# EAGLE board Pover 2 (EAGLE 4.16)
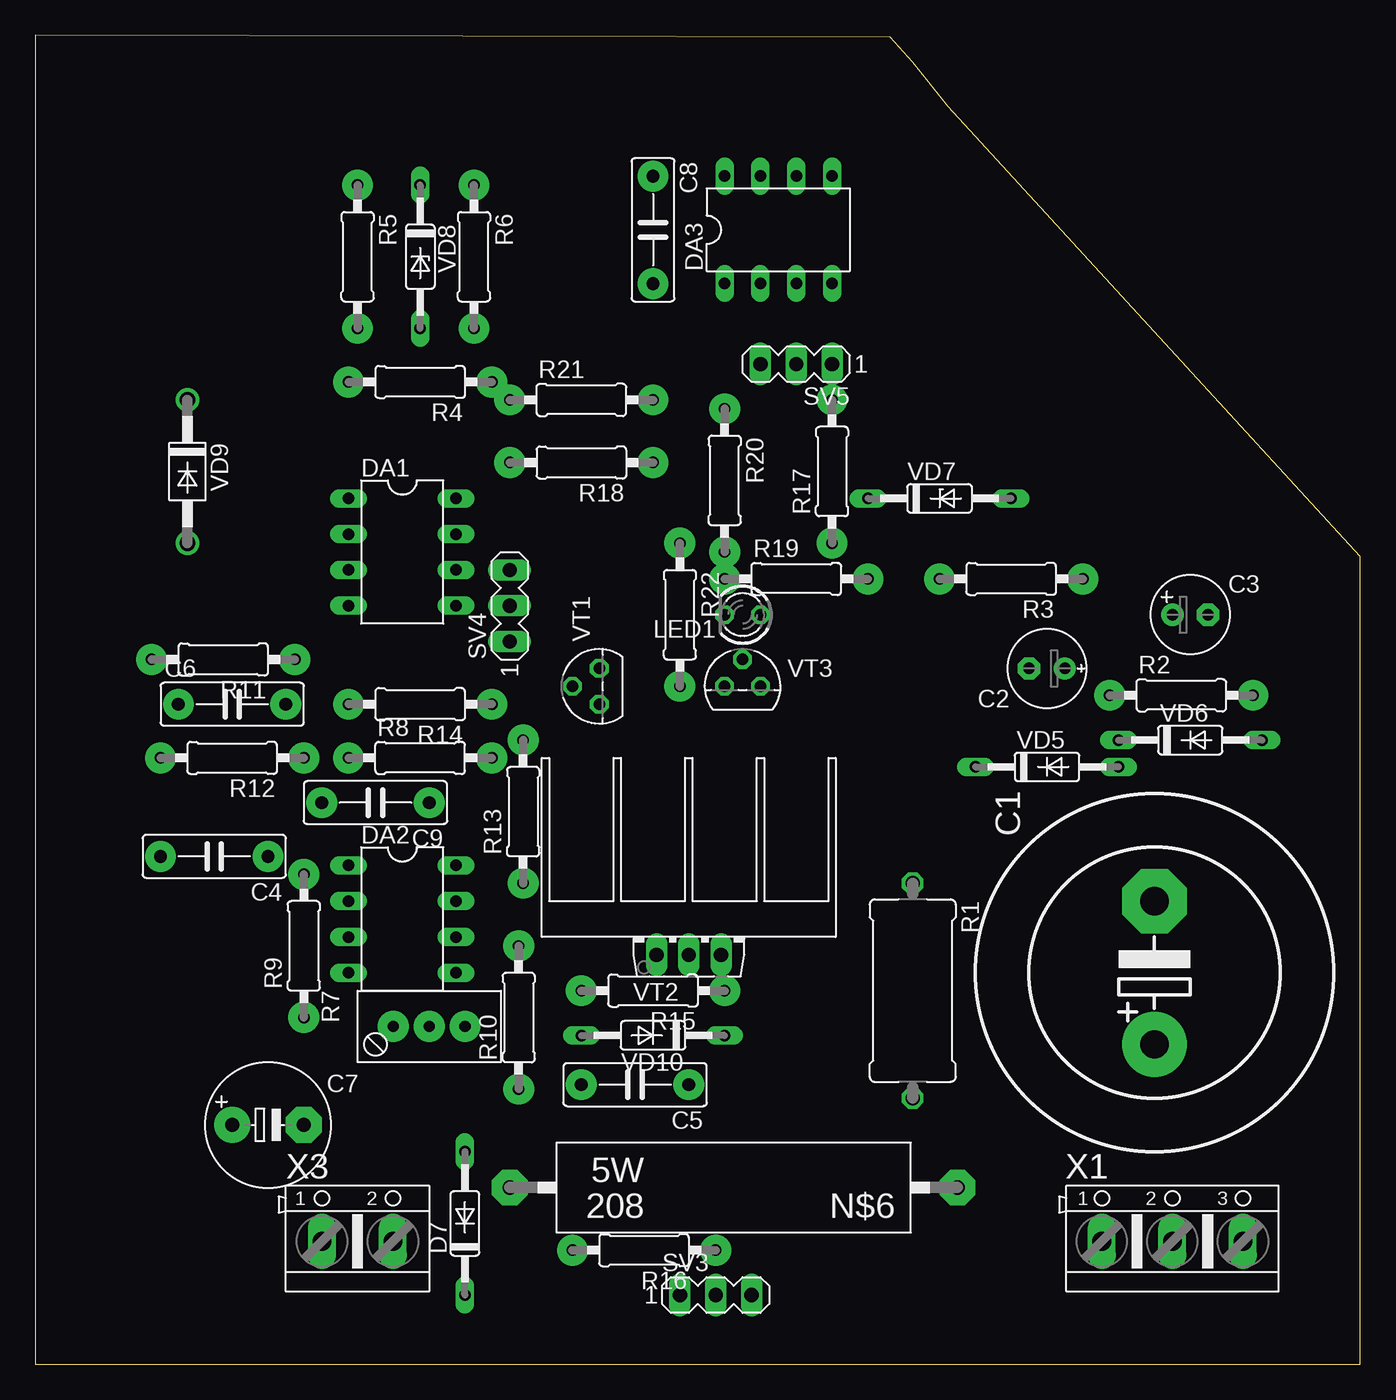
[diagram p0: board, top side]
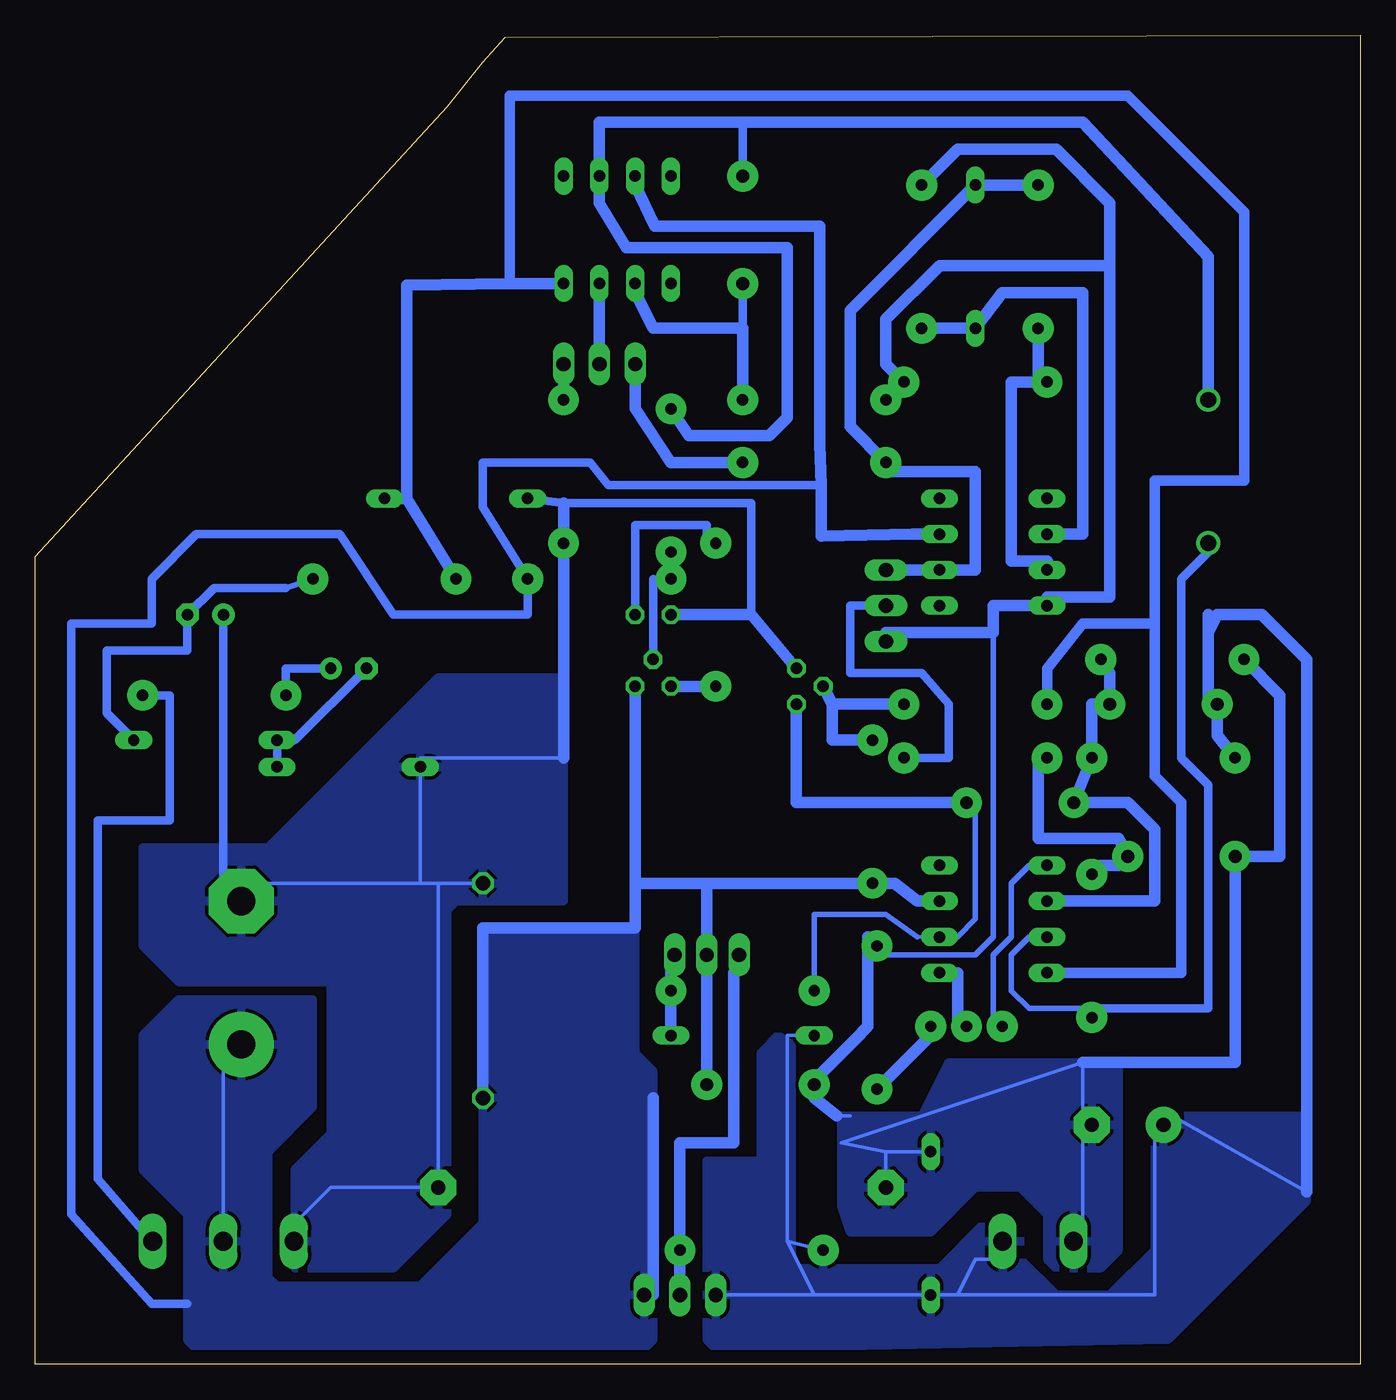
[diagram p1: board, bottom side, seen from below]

Size 93.97 x 94.28 mm. Coordinates in mm from the lower left corner, seen from the top.
Outline: 0,0 93.96,0 93.97,57.3 64.77,89.2 62.23,92.38 60.64,94.13 0,94.28 0,0
Copper layers (1*16): Top 0.035mm / dielectric 1.5mm / Bottom 0.035mm
Design rules "default": minimum track width 10mil, minimum drill 31mil, track to track 8mil, track to pad 8mil, pad to pad 8mil, via to via 8mil, smd to smd 8mil, copper to edge 40mil, drill to drill 8mil, minimum pad ring 10mil, minimum via ring 8mil, stop-mask expansion 0mil, vias tented up to drill 0mil, thermal gap 10mil
Net classes: 1 Pover: width 0.762 mm, drill 0.508 mm, clearance 0.508 mm

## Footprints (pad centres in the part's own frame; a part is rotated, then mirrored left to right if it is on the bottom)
EB25D = drill 2.007 pad 4.597 round: + -5.08,0 | drill 2.007 pad 4.597 octagon: - 5.08,0
E2,5-6E = drill 0.813 pad 1.575 round: + -1.27,0 | drill 0.813 pad 1.575 octagon: - 1.27,0
E2,5-6 = drill 0.813 pad 1.6 round: + -1.27,0 | drill 0.813 pad 1.6 octagon: - 1.27,0
C075-032X103 = drill 0.914 pad 2.184 round: 1 -3.81,0; 2 3.81,0
E5-8,5 = drill 1.016 pad 2.54 round: + -2.54,0 | drill 1.016 pad 2.54 octagon: - 2.54,0
DO35-10 = drill 0.813 long: A 5.08,0; C -5.08,0
DIL08 = drill 0.813 long: 1 -3.81,-3.81; 2 -1.27,-3.81; 3 1.27,-3.81; 4 3.81,-3.81; 5 3.81,3.81; 6 1.27,3.81; 7 -1.27,3.81; 8 -3.81,3.81
LED3MM = drill 0.813 octagon: A -1.27,0; K 1.27,0
KH208-8 = drill 1.016 pad 2.54 octagon: 1 -15.875,0; 2 15.875,0
RDH/15 = drill 1.016 octagon: 1 -7.62,0; 2 7.62,0
0207/10 = drill 0.813 pad 2.184 round: 1 -5.08,0; 2 5.08,0
RT5X10H = drill 0.8 pad 2.184 round: P$1 0,2.54; P$2 0,0; P$3 0,-2.54
MA03-1 = drill 1.016 long: 1 -2.54,0; 2 0,0; 3 2.54,0
DO35Z10 = drill 0.813 long: A 5.08,0; C -5.08,0
DO41-10 = drill 1.118 round: A 5.08,0; C -5.08,0
TO92 = drill 0.813 octagon: 1 1.27,0; 2 0,1.905; 3 -1.27,0
TO126AV = drill 1.016 long: B 2.286,-1.27; C 0,-1.27; E -2.286,-1.27
AK500/3 = drill 1.321 long: 1 -5.004,0; 2 0,0; 3 5.004,0
AK500/2 = drill 1.321 long: 1 -2.515,0; 2 2.515,0

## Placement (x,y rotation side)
C1  [EB25D]  79.37,27.77 90 top
C2  [E2,5-6E]  71.75,49.36 180 top
C3  [E2,5-6]  81.91,53.17 0 top
C4  [C075-032X103]  12.7,36.03 180 top
C5  [C075-032X103]  42.54,19.84 180 top
C6  [C075-032X103]  13.96,46.83 0 top
C7  [E5-8,5]  16.51,16.98 0 top
C8  [C075-032X103]  43.81,80.48 270 top
C9  [C075-032X103]  24.12,39.84 180 top
D7  1N4148  [DO35-10]  30.48,9.99 90 top
DA1  TL081P  [DIL08]  26.03,57.62 270 top
DA2  TL081P  [DIL08]  26.03,31.58 270 top
DA3  TL081P  [DIL08]  52.7,80.48 0 top
LED1  [LED3MM]  50.16,53.17 180 top
N$6  [KH208-8]  49.52,12.53 180 top
R1  [RDH/15]  62.23,26.5 270 top
R2  [0207/10]  81.28,47.46 0 top
R3  [0207/10]  69.21,55.72 180 top
R4  [0207/10]  27.3,69.69 180 top
R5  [0207/10]  22.86,78.57 270 top
R6  [0207/10]  31.11,78.57 270 top
R7  [RT5X10H]  27.94,23.96 90 top
R8  [0207/10]  27.3,43.02 0 top
R9  [0207/10]  19.05,29.68 90 top
R10  [0207/10]  34.29,24.6 90 top
R11  [0207/10]  13.33,50 180 top
R12  [0207/10]  13.96,43.02 180 top
R13  [0207/10]  34.6,39.2 90 top
R14  [0207/10]  27.3,46.83 180 top
R15  [0207/10]  43.81,26.5 180 top
R16  [0207/10]  43.17,8.09 180 top
R17  [0207/10]  56.51,63.34 90 top
R18  [0207/10]  38.73,63.97 180 top
R19  [0207/10]  53.97,55.72 0 top
R20  [0207/10]  48.89,62.7 270 top
R21  [0207/10]  38.73,68.41 0 top
R22  [0207/10]  45.72,53.17 270 top
RAD1  [KK13X22]  46.35,30.31 0 top
SV3  [MA03-1]  48.26,4.91 0 top
SV4  [MA03-1]  33.65,53.81 90 top
SV5  [MA03-1]  53.97,70.95 180 top
VD5  1N4148  [DO35-10]  71.75,42.38 0 top
VD6  1N4148  [DO35-10]  81.91,44.28 0 top
VD7  [DO35Z10]  64.13,61.43 0 top
VD8  [DO35Z10]  27.3,78.57 270 top
VD9  1N4004  [DO41-10]  10.79,63.34 270 top
VD10  1N4148  [DO35-10]  43.81,23.33 180 top
VT1  BC547  [TO92]  40,48.09 90 top
VT2  BD139  [TO126AV]  46.35,30.31 0 top
VT3  BC557  [TO92]  50.16,48.09 0 top
X1  [AK500/3]  80.64,8.72 0 top
X3  [AK500/2]  22.86,8.72 0 top

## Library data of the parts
C1-C9 R1-R22 = rcl
D7 VD5-VD10 = diode
DA1-DA3 = linear
LED1 = led
N$6 = resistor-power
RAD1 = heatsink
SV3-SV5 = con-lstb
VT1 = transistor
VT2 = transistor-power
VT3 = transistor-pnp
X1 X3 = con-ptr500

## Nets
N$1: R19.1 R20.2 VT3.2
N$2: R22.2 VT3.3
N$3: DA3.3 SV5.2
N$4: C8.1 DA3.6 R20.1 VD9.C
N$5: LED1.A R22.1
N$6: C1.+ C5.1 DA1.7 DA2.7 DA3.7 R1.2 R13.1 R19.2 SV3.3 VT2.C VT3.1 X1.2
N$7: C2.+ R2.1
N$8: C3.- R3.1 VD6.A
N$9: C1.- C3.+ LED1.K N$6.1 R1.1 R17.1 VD5.C VD7.C VT1.1 X1.1
N$11: C8.2 DA3.2 R21.2
N$12: R2.2 X1.3
N$14: R18.1 SV5.3
N$15: R17.2 SV5.1
N$16: DA1.6 R5.1 R18.2 SV4.3 VD8.C
N$17: DA1.3 R4.2 R5.2
N$18: DA1.2 R6.2 VD8.A
N$19: C4.1 R8.1 R9.2
N$20: R8.2 SV4.2
N$21: C4.2 C5.2 C7.- D7.A DA1.4 N$6.2 R4.1 R6.1 R10.2 R11.2 R21.1 SV4.1 X3.1
N$22: DA2.3 R9.1 VD9.A
N$24: C6.2 C9.2 DA2.2 R11.1 R12.1
N$25: R13.2 R14.1 VT1.2
N$26: R16.1 SV3.2 VT2.E
N$27: C9.1 DA2.6 R15.2 VT1.3
N$28: DA2.1 R7.P$1
N$29: DA2.5 R7.P$2
N$30: R7.P$3 R10.1
N$31: C6.1 C7.+ D7.C R12.2 R16.2 SV3.1 VD10.A X3.2
N$32: R15.1 VD10.C VT2.B
N$35 [Pover]: DA2.4 DA3.4 R3.2 R14.2 VD7.A
VD5: C2.- VD5.A VD6.C

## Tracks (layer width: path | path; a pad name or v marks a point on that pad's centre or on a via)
N$1
  Bottom 0.406: 50.16,55.72 R19.1
  Bottom 0.61: VT3.2 50.16,55.72 | R19.1 R20.2
N$2
  Bottom 0.813: R22.2 VT3.3
N$3
  Bottom 0.813: SV5.2 DA3.3
N$4
  Bottom 0.61: 43.81,88.1 C8.1
  Bottom 0.813: VD9.C 10.79,78.57 19.68,88.1 43.81,88.1 53.97,88.1 DA3.6 53.97,82.38 52.06,79.21 40.63,79.21 40.63,67.14 41.91,65.88 47.62,65.88 R20.1
N$5
  Bottom 0.61: LED1.A 51.43,59.52 46.35,59.52 46.35,58.25 R22.1
N$6
  Bottom 0.254: 50.16,4.91 SV3.3 | X1.2 80.64,21.42 C1.+
  Bottom 0.406: 51.43,83.66 DA3.7
  Bottom 0.61: 38.22,62.37 53.34,62.37 54.61,63.97 62.23,63.97 62.23,60.8 R19.2 59.05,53.17 68.58,53.17 72.38,58.89 82.55,58.89 85.72,55.72 85.72,52.54 91.44,52.54 91.44,10.63 85.72,4.28 83.18,4.28
  Bottom 0.813: DA2.7 31.43,32.85 33.02,34.12 R13.1 46.35,34.12 | 46.35,34.12 VT2.C C5.1 | R1.2 62.23,30.95 51.43,30.95 51.43,34.12 | 46.35,34.12 51.43,34.12 | 51.43,34.12 VT3.1 | DA1.7 31.75,58.89 38.22,58.76 38.22,62.37 38.35,65.24 38.35,80.73 50.03,80.73 51.43,83.66 | 50.16,18.88 50.16,4.91
  pour Bottom: 77.47,14.44 77.47,15.07 74.29,18.25 74.29,25.87 83.81,25.87 86.36,23.33 86.36,13.8 83.18,10.63 83.18,1.74 81.91,0.47 51.43,0.47 50.16,1.74 50.16,20.79 50.8,21.42 51.43,22.06 51.43,30.95 62.23,30.95 62.23,9.99 66.67,5.55 76.83,5.55 77.47,6.18 77.47,15.07
N$7
  Bottom 0.61: C2.+ 76.19,49.36 R2.1
N$8
  Bottom 0.406: 76.19,55.08 R3.1
  Bottom 0.61: VD6.A 88.9,46.19 88.9,50.63 83.18,50.63 C3.- 81.28,55.08 76.19,55.08
N$9
  Bottom 0.254: 80.64,34.12 C1.- 78.1,34.12 66.67,34.12 | 65.4,34.12 66.67,34.12 | 66.67,34.12 VD5.C 66.67,43.02 56.51,43.02 | 65.4,34.12 R1.1 | 65.4,34.12 N$6.1 73.02,12.53 75.56,9.99 X1.1
  Bottom 0.61: 80.64,34.12 C3.+ | 43.2,53.17 43.2,61.1 56.51,61.1 VD7.C
  Bottom 0.813: VT1.1 43.2,53.17 LED1.K | 56.51,61.1 R17.1 56.51,43.02
  pour Bottom: 73.02,27.14 73.02,16.34 75.56,13.8 75.56,6.82 68.58,6.82 64.77,10.63 64.77,32.22 64.13,32.85 56.51,32.85 56.51,48.73 65.4,48.73 77.47,36.66 86.36,36.66 86.36,29.68 83.81,27.14
N$11
  Bottom 0.406: 51.43,76.03 DA3.2
  Bottom 0.61: 43.81,73.5 C8.2
  Bottom 0.813: R21.2 43.81,73.5 50.16,73.5 51.43,76.03
N$12
  Bottom 0.254: X1.3 85.72,8.72
  Bottom 0.61: 85.72,8.72 89.53,13.17 89.53,38.57 84.45,38.57 84.45,47.46 R2.2
N$14
  Bottom 0.813: R18.1 48.89,63.97 51.43,67.78 SV5.3
N$15
  Bottom 0.813: R17.2 SV5.1
N$16
  Bottom 0.254: 33.65,63.34 R18.2
  Bottom 0.813: R5.1 VD8.C 36.19,74.77 36.19,66.51 R18.2 | 30.48,56.35 SV4.3 34.29,56.35 | 30.48,56.35 27.3,56.35 27.3,63.34 33.65,63.34 | 30.48,56.35 DA1.6
N$17
  Bottom 0.406: DA1.3 22.22,56.98
  Bottom 0.813: 22.22,56.98 24.76,56.98 24.76,69.69 22.86,69.69 | 22.86,69.69 R4.2 | 22.86,69.69 R5.2
N$18
  Bottom 0.813: DA1.2 19.68,58.89 19.68,76.03 25.4,76.03 VD8.A R6.2
N$19
  Bottom 0.254: C4.1 17.14,35.39 | 18.41,35.39 R9.2 | R8.1 22.86,43.02
  Bottom 0.813: 17.14,35.39 18.41,35.39 | 22.86,43.02 22.86,37.3 17.14,37.3 C4.1
N$20
  Bottom 0.254: SV4.2 33.65,54.45
  Bottom 0.61: SV4.2 36.19,53.81 36.19,49.05 31.11,49.05 29.2,46.83 29.2,43.02 R8.2
N$21
  Bottom 0.254: 34.92,30.31 R10.2 | 33.65,15.07 36.83,15.71 19.68,21.42 19.68,17.61 C7.- 19.68,16.34 19.68,9.99 X3.1 | 33.65,15.07 N$6.2 | 33.65,15.07 D7.A | 37.14,17.61 36.19,17.61 | 38.73,20.15 C5.2
  Bottom 0.406: DA1.4 22.22,54.45 | 26.03,51.91 26.03,30.31 27.3,29.04 34.92,29.04 | 33.65,51.91 SV4.1
  Bottom 0.813: R21.1 32.38,69.05 R4.1 33.65,70.95 33.65,74.13 29.84,77.94 17.78,77.94 | R6.1 28.57,86.19 21.59,86.19 17.78,82.38 17.78,77.94 | 17.78,77.94 17.78,54.45 22.22,54.45 | DA1.4 26.03,53.81 26.03,51.91 33.65,51.91 | 34.92,30.31 34.92,29.04 34.92,23.96 35.87,23.01 | 35.87,23.01 36.83,22.06 | R11.2 5.71,47.46 5.71,36.03 C4.2 8.89,21.42 19.68,21.42 | 37.14,17.61 38.73,18.88 C5.2 | 35.87,23.01 38.73,20.15
  pour Bottom: 36.83,17.61 31.11,17.61 29.2,21.42 17.14,21.42 17.14,8.09 18.41,6.82 21.59,6.82 22.22,7.45 22.22,10.63 24.12,12.53 27.3,12.53 30.48,9.36 36.19,9.36 36.83,11.26
N$22
  Bottom 0.254: 23.49,30.31 DA2.3 | 19.05,25.23 R9.1
  Bottom 0.406: 23.49,30.31 24.76,29.04 24.76,26.5 23.49,25.23 19.05,25.23
  Bottom 0.61: 19.05,25.23 10.79,25.23 10.79,41.11 12.7,43.02 12.7,55.72 10.79,57.62 VD9.A
N$24
  Bottom 0.813: R11.1 17.78,49.05 C6.2 19.05,46.83 R12.1 C9.2 16.51,39.84 14.6,37.94 14.6,32.85 DA2.2
N$25
  Bottom 0.813: R14.1 37.46,46.83 | 37.46,46.83 VT1.2 | 37.46,46.83 37.46,44.28 R13.2
N$26
  Bottom 0.254: 44.45,27.77 VT2.E | SV3.2 48.89,4.91
  Bottom 0.406: R16.1 48.26,7.45
  Bottom 0.813: 48.26,7.45 SV3.2 | R16.1 48.26,15.71 44.45,15.71 44.45,27.77
N$27
  Bottom 0.254: 31.43,30.31 DA2.6 28.57,30.31
  Bottom 0.406: R15.2 38.73,31.9 33.65,31.9 31.43,30.31 | 28.57,30.31 27.3,31.58 27.3,39.84 29.84,39.84
  Bottom 0.813: VT1.3 40,39.84 29.84,39.84 C9.1
N$28
  Bottom 0.254: 23.49,35.39 DA2.1 | 26.03,23.96 R7.P$1
  Bottom 0.406: 23.49,35.39 24.76,34.12 24.76,30.31 26.03,29.04 26.03,23.96
N$29
  Bottom 0.406: 28.57,23.96 R7.P$2
  Bottom 0.813: 28.57,23.96 28.57,27.77 DA2.5
N$30
  Bottom 0.406: 33.65,20.15 R10.1 | R7.P$3 29.84,23.96
  Bottom 0.813: 29.84,23.96 33.65,20.15
N$31
  Bottom 0.254: 40.63,8.72 40.63,23.33 VD10.A | 38.73,4.91 40.63,8.72 | 38.73,4.91 SV3.1 | 28.57,4.91 27.3,7.45 26.03,7.45 X3.2 | 28.57,4.91 D7.C 38.73,4.91 | 28.57,4.91 14.6,4.91 14.6,16.34 C7.+ 13.33,17.61 3.8,12.22 | 40.63,8.72 R16.2
  Bottom 0.61: 10.79,46.83 C6.1
  Bottom 0.813: C6.1 10.16,44.6 R12.2 | 10.79,51.91 10.79,46.83 | 10.79,51.91 10.16,53.17 6.98,53.17 3.8,50 3.8,12.22 | 10.79,53.17 10.79,51.91
  pour Bottom: 40.32,22.7 41.27,23.33 42.54,22.06 42.54,14.44 46.35,14.44 46.35,1.74 45.72,1.1 13.65,1.74 3.8,11.58 3.8,17.61 12.7,17.61 14.6,15.71 14.6,8.09 17.78,4.91 21.59,4.91 24.12,7.45 24.12,9.99 26.66,9.99 29.84,6.82 40.32,6.82
N$32
  Bottom 0.813: VD10.C R15.1 48.89,27.77 VT2.B
N$35
  Bottom 0.762: 14.6,52.54 19.68,52.54 22.22,49.36 R14.2 | 14.6,52.54 14.6,41.74 12.7,39.84 12.7,27.77 DA2.4 | 14.6,52.54 14.6,62.7 8.25,62.7 8.25,81.75 16.51,90 60.32,90 60.32,76.67
  Bottom 0.813: 67.62,61.43 67.62,76.54 60.32,76.67 DA3.4 | 67.62,61.43 R3.2 | 67.62,61.43 VD7.A
VD5
  Bottom 0.61: VD5.A VD6.C 75.56,44.28 C2.-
